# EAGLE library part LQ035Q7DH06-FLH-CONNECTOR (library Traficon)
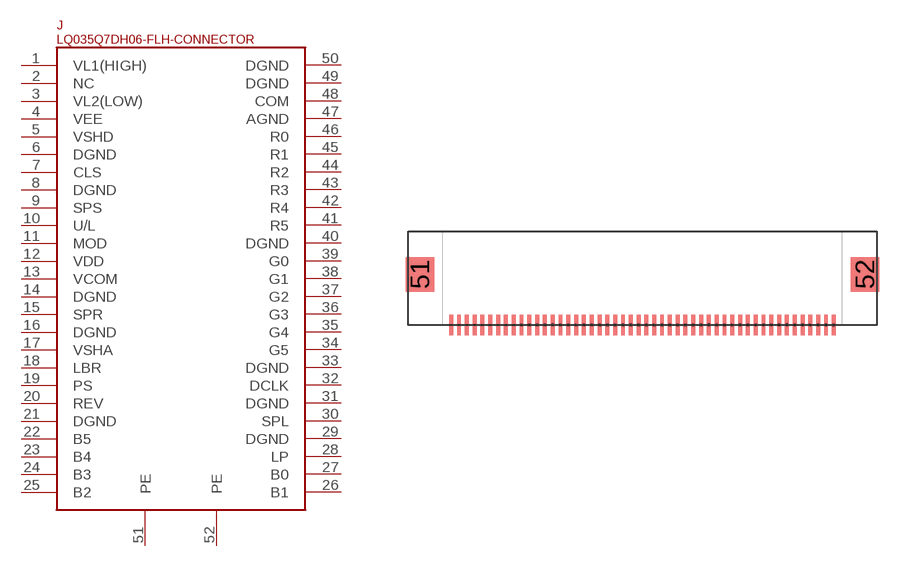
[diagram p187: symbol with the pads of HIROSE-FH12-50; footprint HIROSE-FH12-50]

Designator prefix J

## LQ035Q7DH06-FLH-CONNECTOR  [HIROSE-FH12-50]
1  VL1(HIGH)  in
2  NC  nc
3  VL2(LOW)  in
4  VEE  pwr
5  VSHD  pwr
6  DGND  pwr
7  CLS  in
8  DGND  pwr
9  SPS  in
10  U/L  in
11  MOD  in
12  VDD
13  VCOM  in
14  DGND  pwr
15  SPR
16  DGND  pwr
17  VSHA  pwr
18  LBR  in
19  PS  in
20  REV  in
21  DGND  pwr
22  B5  in
23  B4  in
24  B3  in
25  B2  in
26  B1  in
27  B0  in
28  LP  in
29  DGND  pwr
30  SPL
31  DGND  pwr
32  DCLK  in
33  DGND  pwr
34  G5  in
35  G4  in
36  G3  in
37  G2  in
38  G1  in
39  G0  in
40  DGND  pwr
41  R5  in
42  R4  in
43  R3  in
44  R2  in
45  R1  in
46  R0  in
47  AGND  pwr
48  COM  out
49  DGND  pwr
50  DGND  pwr
51  PE
52  PE

## Footprint HIROSE-FH12-50 (pad centres in mm)
smd 0.25 x 1.3: 1 -12.25,0; 2 -11.75,0; 3 -11.25,0; 4 -10.75,0; 5 -10.25,0; 6 -9.75,0; 7 -9.25,0; 8 -8.75,0; 9 -8.25,0; 10 -7.75,0; 11 -7.25,0; 12 -6.75,0; 13 -6.25,0; 14 -5.75,0; 15 -5.25,0; 16 -4.75,0; 17 -4.25,0; 18 -3.75,0; 19 -3.25,0; 20 -2.75,0; 21 -2.25,0; 22 -1.75,0; 23 -1.25,0; 24 -0.75,0; 25 -0.25,0; 26 0.25,0; 27 0.75,0; 28 1.25,0; 29 1.75,0; 30 2.25,0; 31 2.75,0; 32 3.25,0; 33 3.75,0; 34 4.25,0; 35 4.75,0; 36 5.25,0; 37 5.75,0; 38 6.25,0; 39 6.75,0; 40 7.25,0; 41 7.75,0; 42 8.25,0; 43 8.75,0; 44 9.25,0; 45 9.75,0; 46 10.25,0; 47 10.75,0; 48 11.25,0; 49 11.75,0; 50 12.25,0
smd 1.8 x 2.2: 51 -14.25,3.25; 52 14.25,3.25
